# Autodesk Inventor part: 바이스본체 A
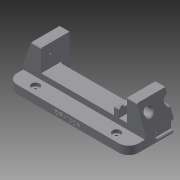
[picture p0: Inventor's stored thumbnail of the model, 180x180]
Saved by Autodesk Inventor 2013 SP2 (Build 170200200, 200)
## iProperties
Created: 2017-04
Part Number: 바이스본체 A
Material: 일반
Document SubType Name: Modeling
Designer: mduedu
Density: 1 g/cm^3
Author: mduedu
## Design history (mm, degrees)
sketch "스케치1"
  geometry: L1 (-75, 0)-(75, 0); L2 (-75, 0)-(-75, 17); L3 (-53, 17)-(53, 17); L4 (75, 17)-(75, 0); L5 (-75, 17)-(-65.173, 44); L6 (-65.173, 44)-(-53, 44); L7 (-53, 44)-(-53, 17); L8 (0, 0)-(0, 17); L9 (75, 17)-(65.173, 44); L10 (65.173, 44)-(53, 44); L11 (53, 44)-(53, 17); 1 further point
  constraints: 22 end point, 4 perpendicular, 2 horizontal alignment, 2 midpoint, 2 symmetric about line, 1 coincident, 1 collinear, 1 horizontal, 1 vertical
  dimensions: "d0" = 150 distance of L1.start L1.end; "d1" = 17 distance of L1.start L2.end; "d2" = 27 distance of L3.start L6.end; "d3" = 22 distance of L3.start L2.end; "d4" = 70 deg angle of L3 L5; "d54" = 20 deg angle of L9 L4
extrude "돌출1" new body sketch "스케치1" stored distance "d5" = 70; taper "d6" = 0 deg
sketch "스케치2"
  geometry: L1 (0, 70)-(106, 70) reference; L2 (106, 70)-(106, 0) reference; L3 (106, 0)-(0, 0) reference; L4 (0, 47)-(106, 47); L5 (106, 47)-(106, 23); L6 (106, 23)-(0, 23); L7 (0, 23)-(0, 47); L8 (0, 70)-(0, 0) reference; 2 further points
  constraints: 8 end point, 2 parallel, 2 point on line, 1 horizontal, 1 horizontal alignment, 1 midpoint, 1 perpendicular
  dimensions: "d7" = 24 distance between parallel lines of L6 L4
extrude "돌출2" cut sketch "스케치2" stored distance "d9" = 70; taper "d10" = 0 deg
sketch "스케치3"
  geometry: L1 (22, -23)-(128, -23) reference; L2 (128, -47)-(22, -47) reference; L3 (22, -18)-(128, -18); L4 (128, -52)-(22, -52); L5 (22, -18)-(22, -52); L6 (128, -18)-(128, -52); 1 further point
  constraints: 8 end point, 3 parallel, 2 point on line, 1 perpendicular
  dimensions: "d11" = 5 distance between parallel lines of L3 L1; "d12" = 5 distance between parallel lines of L4 L2
extrude "돌출3" cut sketch "스케치3" distance "d13" = 12; taper "d14" = 0 deg
fillet "모깎기1" dims "d15" = 3, "d16" = 3
sketch "스케치4"
  geometry: L1 (103, 23)-(3, 23) reference; L2 (0, 26)-(0, 0) reference; L3 (106, 0)-(0, 0) reference; L4 (106, 26)-(106, 0) reference; L5 (96, 0)-(90, 0); L6 (90, 0)-(90, 19.5); L7 (96, 19.5)-(96, 0); L8 (90, 19.5)-(96, 19.5); A1 r 3 centre (3, 26) between (0, 26) and (3, 23) reference; A2 r 3 centre (103, 26) between (103, 23) and (106, 26) reference; 1 further point
  constraints: 8 end point, 2 perpendicular, 1 horizontal, 1 parallel, 1 point on line
  dimensions: "d17" = 10 distance between parallel lines of L7 L4; "d18" = 6 distance between parallel lines of L7 L6; "d27" = 3.5 distance between parallel lines of L8 L1
extrude "돌출4" join sketch "스케치4" distance "d19" = 12; taper "d20" = 0 deg
chamfer "모따기1" distance "d21" = 3; stored, may be unused: second distance "d22" = 2, angle "d23" = 45 deg
chamfer "모따기2" distance "d24" = 3; stored, may be unused: second distance "d25" = 2, angle "d26" = 45 deg
sketch "스케치5"
  geometry: L1 (-15.5, 35.8)-(-15.5, -25.8) reference; L2 (19.5, 0)-(0, 0) reference; C1 r 6.5 at (9.5, 15); 1 further point
  constraints: 1 centre point
  dimensions: "d28" = 13 diameter of C1; "d30" = 15 distance from line of C1.centre L2; "d31" = 25 distance from line of C1.centre L1
extrude "돌출5" cut sketch "스케치5" stored distance "d32" = 12; taper "d33" = 0 deg
sketch "스케치6"
  geometry: C1 r 5 at (-10, 15); C2 r 5 at (-60, 15); A1 r 6.5 centre (-10, 15) between (-15.766, 12) and (-4.234, 12) reference; A2 r 6.5 centre (-60, 15) between (-65.766, 12) and (-54.234, 12) reference; 1 further point
  constraints: 2 centre point, 2 coincident
  dimensions: "d34" = 10 diameter of C1; "d35" = 10 diameter of C2 (= d34)
extrude "돌출6" cut sketch "스케치6" stored distance "d36" = 12; taper "d37" = 0 deg
chamfer "모따기3" distance "d38" = 1; stored, may be unused: second distance "d39" = 2, angle "d40" = 45 deg
chamfer "모따기4" distance "d41" = 1; stored, may be unused: second distance "d42" = 2, angle "d43" = 45 deg
sketch "스케치7"
  geometry: L1 (-35, 35.8)-(-35, -25.8) reference; L2 (-70, 0)-(0, 0) reference; C1 r 5 at (-35, 15); 1 further point
  constraints: 1 centre point, 1 point on line
  dimensions: "d44" = 10 diameter of C1; "d45" = 15 distance from line of C1.centre L2
extrude "돌출7" cut sketch "스케치7" stored distance "d46" = 12; taper "d47" = 0 deg
chamfer "모따기5" distance "d48" = 1; stored, may be unused: second distance "d49" = 2, angle "d50" = 45 deg
node "작업축1"
sketch "스케치8"
  geometry: L1 (-105, 32)-(105, 32) reference; L2 (58, 32)-(64, 32); L3 (64, 32)-(64, 40); L4 (64, 40)-(58, 40); L5 (58, 40)-(58, 32); L6 (53, 38)-(53, 26) reference; 1 further point
  constraints: 8 end point, 2 parallel, 1 horizontal, 1 perpendicular, 1 point on line
  dimensions: "d51" = 5 distance from line of L6 L2.start; "d52" = 6 distance of L3.end L4.end; "d53" = 16 diameter of L4 L1
revolve "회전1" sketch "스케치8" stored, may be unused: angle "d55" = 90 deg
fillet "모깎기2"
chamfer "모따기6" distance "d56" = 1; stored, may be unused: second distance "d57" = 2, angle "d58" = 45 deg
sketch "스케치9"
  geometry: L1 (17.5, 3)-(52.5, 3); L2 (52.5, 13)-(17.5, 13); L3 (70, 0)-(0, 0) reference; L4 (17.5, 8)-(52.5, 8); A1 r 5 centre (17.5, 8) between (17.5, 13) and (17.5, 3); A2 r 5 centre (52.5, 8) between (52.5, 3) and (52.5, 13); 3 further points
  constraints: 6 end point, 4 point on circle, 3 tangent, 2 centre point, 2 midpoint, 2 parallel, 1 horizontal, 1 vertical alignment
  dimensions: "d59" = 35 distance of L4.start L4.end; "d61" = 5 radius of A2; "d62" = 8 distance between parallel lines of L3 L4
extrude "돌출8" cut sketch "스케치9" distance "d63" = 3; taper "d64" = 0 deg
chamfer "모따기7" distance "d65" = 1; stored, may be unused: second distance "d66" = 2, angle "d67" = 45 deg
chamfer "모따기8" distance "d68" = 1; stored, may be unused: second distance "d69" = 2, angle "d70" = 45 deg
feature "분할1"
sketch "스케치10"
  geometry: L1 (35, 27)-(0, 27) reference; L2 (0, 0)-(0, 27) reference; 1 further point
  dimensions: "d85" = 11.5 distance from line of point (12, 15.5) L1; "d86" = 12 distance from line of point (12, 15.5) L2
hole "구멍1" sketch "스케치10" at (12, 15.5) diameter "d71" = 3.242; stored, may be unused: countersink angle "d75" = 90 deg, drill point angle "d77" = 120 deg; dims "d72" = 8, "d73" = 4, "d74" = 2, "d76" = 10
sketch "스케치11"
  geometry: A1 r 5 centre (17.5, 8) between (17.5, 13) and (17.5, 3) reference; 1 further point
  constraints: 1 coincident
hole "구멍3" sketch "스케치11" at (17.5, 8) diameter "d78" = 2.459; stored, may be unused: countersink angle "d82" = 90 deg, drill point angle "d84" = 120 deg; dims "d79" = 4.5, "d80" = 4, "d81" = 2, "d83" = 6
sketch "스케치13"
  geometry: L1 (75, 0)-(75, 35) reference; L2 (-75, 0)-(-75, 35) reference; L3 (-75, 35)-(75, 35); L4 (75, 35)-(75, 55); L5 (75, 55)-(-75, 55); L6 (-75, 55)-(-75, 35); 1 further point
  constraints: 8 end point, 2 parallel, 1 horizontal, 1 perpendicular, 1 point on line
  dimensions: "d90" = 20 distance between parallel lines of L5 L3; "d94" = 150 distance of L4.end L5.end (derived)
extrude "돌출9" join sketch "스케치13" distance "d92" = 10; taper "d93" = 0 deg
sketch "스케치14"
  geometry: L1 (-75, -35)-(-75, -55) reference; L2 (75, -55)-(75, -35) reference; L3 (-75, -45)-(75, -45); 3 further points
  constraints: 2 end point, 2 midpoint, 2 point on line
  dimensions: "d95" = 50 horizontal distance of point (-50, -45) point (0, 0); "d96" = 100 distance of point (50, -45) point (-50, -45)
fillet "모깎기3" dims "d97" = 12
chamfer "모따기9" distance "d98" = 1; stored, may be unused: second distance "d99" = 2, angle "d100" = 45 deg
hole "구멍4" sketch "스케치14" diameter "d101" = 4.134; stored, may be unused: countersink angle "d105" = 90 deg, drill point angle "d107" = 118 deg; dims "d102" = 6, "d103" = 10, "d104" = 4, "d106" = 8
sketch "스케치15"
  geometry: L1 (0, 0)-(126, 0) reference; 3 further points
  constraints: 1 midpoint, 1 vertical alignment, 1 other
  dimensions: "d109" = 5 distance from line of point (63, 5) L1
feature "엠보싱2" sketch "스케치15" dims "d0" = 150, "d1" = 17, "d2" = 27, "d3" = 22, "d4" = 70 deg, "d54" = 20 deg, "d110" = 0.5, "d111" = 0
node "솔리드1"
mirror "대칭1"
mirror "대칭2"
mirror "대칭3"
mirror "대칭4"
node "투영된 루프1"
